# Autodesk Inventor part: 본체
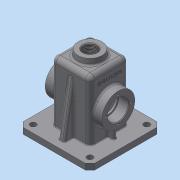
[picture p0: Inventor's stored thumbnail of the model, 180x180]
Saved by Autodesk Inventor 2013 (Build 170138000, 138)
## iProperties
Created: 2018-10
Part Number: 본체
Material: 일반
Document SubType Name: Modeling
Designer: Administrator
Density: 1 g/cm^3
Mass: 294.038 g
Surface Area: 900.166 cm^2
Volume: 294.038 cm^3
Author: Administrator
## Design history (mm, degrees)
sketch "스케치1"
  geometry: L1 (-32.5, -32.5)-(32.5, -32.5); L2 (32.5, -32.5)-(32.5, 32.5); L3 (32.5, 32.5)-(-32.5, 32.5); L4 (-32.5, 32.5)-(-32.5, -32.5); L5 (-32.5, -32.5)-(32.5, 32.5); L6 (32.5, -32.5)-(-32.5, 32.5); 1 further point
  constraints: 12 end point, 2 midpoint, 2 parallel, 1 horizontal, 1 perpendicular
  dimensions: "d0" = 65 distance of L3.end L2.end; "d1" = 65 distance of L2.end L1.end
extrude "돌출1" new body sketch "스케치1" stored distance "d2" = 110; taper "d3" = 0 deg
feature "쉘1" dims "d4" = 5
sketch "스케치2"
  geometry: L1 (-32.5, -32.5)-(32.5, -32.5) reference; L2 (32.5, -32.5)-(32.5, 32.5) reference; L3 (32.5, 32.5)-(-32.5, 32.5) reference; L4 (-32.5, 32.5)-(-32.5, -32.5) reference; L5 (-60, -60)-(60, -60); L6 (60, -60)-(60, 60); L7 (60, 60)-(-60, 60); L8 (-60, 60)-(-60, -60); L9 (-60, -60)-(60, 60); L10 (60, -60)-(-60, 60); 1 further point
  constraints: 12 end point, 2 midpoint, 2 parallel, 1 horizontal, 1 perpendicular
  dimensions: "d5" = 120 distance of L7.end L6.end; "d6" = 120 distance of L6.end L5.end
extrude "돌출2" join sketch "스케치2" distance "d7" = 10; taper "d8" = 0 deg
node "작업 평면1"
sketch "스케치3"
  geometry: C1 r 20 at (0, 0); 1 further point
  constraints: 1 centre point, 1 coincident
  dimensions: "d10" = 40 diameter of C1
extrude "돌출3" join sketch "스케치3" stored distance "d11" = 10; taper "d12" = 7 deg
fillet "모깎기1" dims "d13" = 8
node "작업 평면2"
sketch "스케치5"
  geometry: C1 r 27.5 at (47, 24.5); 1 further point
  constraints: 1 centre point, 1 coincident
  dimensions: "d15" = 55 diameter of C1
extrude "돌출4" join sketch "스케치5" stored distance "d16" = 10; taper "d17" = 0 deg
sketch "스케치6"
  geometry: C1 r 27.5 at (0, 0) reference
hole "구멍1" sketch "스케치6" at (0, 0) diameter "d18" = 30; stored, may be unused: countersink angle "d22" = 90 deg, drill point angle "d24" = 0 deg; dims "d19" = 6, "d20" = 35, "d21" = 17, "d23" = 8
sketch "스케치7"
  geometry: L1 (0, 0)-(-21, 0); C1 r 27.5 at (0, 0) reference; 1 further point
  constraints: 2 end point, 1 coincident, 1 horizontal
  dimensions: "d25" = 21 distance of L1.start L1.end
hole "구멍2" sketch "스케치7" at (-21, 0) diameter "d26" = 3.459; stored, may be unused: countersink angle "d30" = 90 deg, drill point angle "d32" = 118 deg; dims "d27" = 8, "d28" = 35, "d29" = 17, "d31" = 10
fillet "모깎기2" dims "d36" = 3
fillet "모깎기3" dims "d37" = 3
sketch "스케치8"
  geometry: C1 r 20 at (0, 0) reference
hole "구멍3" sketch "스케치8" at (0, 0) diameter "d38" = 22.835; stored, may be unused: countersink angle "d42" = 90 deg, drill point angle "d44" = 118 deg; dims "d39" = 8, "d40" = 35, "d41" = 17, "d43" = 10
sketch "스케치9"
  geometry: L1 (42.358, -13)-(48, -45); L2 (60, -45)-(-60, -45) reference; L3 (60, -55)-(60, -45) reference; 1 further point
  constraints: 2 end point, 1 point on line
  dimensions: "d46" = 10 deg angle of L1 L3; "d47" = 12 distance from line of L1.end L3
feature "리브1" sketch "스케치9" dims "d48" = 1, "d49" = 10, "d50" = 0, "d51" = 0, "d52" = 1, "d53" = 1
sketch "스케치10"
  geometry: L1 (42.5, -31)-(42.5, -45); L2 (27.5, 50)-(27.5, -55) reference; L3 (30.5, -15)-(30.5, -17.5) reference; L4 (30.5, -17.5)-(47.5, -17.5) reference; L5 (47.5, -17.5)-(47.5, -19.271) reference; L6 (47.5, -19.271)-(37.5, -19.271) reference; L7 (37.5, -19.271)-(36.461, -21) reference; L8 (36.461, -21)-(37.5, -22.73) reference; L9 (37.5, -22.73)-(47.5, -22.73) reference; L10 (47.5, -22.73)-(47.5, -27.5) reference; L11 (47.5, -27.5)-(35.5, -27.5) reference; L12 (32.5, -30.5)-(32.5, -45) reference; L13 (32.5, -45)-(60, -45) reference; L14 (60, -45)-(60, -55) reference; L15 (60, -55)-(27.5, -55) reference; L16 (27.5, -55)-(27.5, -15) reference; L17 (27.5, -15)-(30.5, -15) reference; L18 (36.461, 21)-(37.5, 19.271) reference; L19 (37.5, 19.271)-(47.5, 19.271) reference; L20 (47.5, 19.271)-(47.5, 17.5) reference; L21 (47.5, 17.5)-(30.5, 17.5) reference; L22 (30.5, 17.5)-(30.5, 15) reference; L23 (30.5, 15)-(27.5, 15) reference; L24 (27.5, 15)-(27.5, 50) reference; L25 (27.5, 50)-(11.418, 50) reference; L26 (11.418, 50)-(11.418, 65) reference; L27 (11.418, 65)-(20, 65) reference; L28 (20, 65)-(21.228, 55) reference; L29 (21.228, 55)-(24.5, 55) reference; L30 (32.5, 47)-(32.5, 30.5) reference; L31 (35.5, 27.5)-(47.5, 27.5) reference; L32 (47.5, 27.5)-(47.5, 22.73) reference; L33 (47.5, 22.73)-(37.5, 22.73) reference; L34 (37.5, 22.73)-(36.461, 21) reference; L35 (-30.5, -17.5)-(-30.5, -15) reference; L36 (-30.5, -15)-(-27.5, -15) reference; L37 (-27.5, -15)-(-27.5, -55) reference; L38 (-27.5, -55)-(-60, -55) reference; L39 (-60, -55)-(-60, -45) reference; L40 (-60, -45)-(-32.5, -45) reference; L41 (-32.5, -45)-(-32.5, -30.5) reference; L42 (-35.5, -27.5)-(-47.5, -27.5) reference; L43 (-47.5, -27.5)-(-47.5, -22.73) reference; L44 (-47.5, -22.73)-(-37.5, -22.73) reference; L45 (-37.5, -22.73)-(-36.461, -21) reference; L46 (-36.461, -21)-(-37.5, -19.271) reference; L47 (-37.5, -19.271)-(-47.5, -19.271) reference; L48 (-47.5, -19.271)-(-47.5, -17.5) reference; L49 (-47.5, -17.5)-(-30.5, -17.5) reference; L50 (-30.5, 15)-(-30.5, 17.5) reference; L51 (-30.5, 17.5)-(-47.5, 17.5) reference; L52 (-47.5, 17.5)-(-47.5, 19.271) reference; L53 (-47.5, 19.271)-(-37.5, 19.271) reference; L54 (-37.5, 19.271)-(-36.461, 21) reference; L55 (-36.461, 21)-(-37.5, 22.73) reference; L56 (-37.5, 22.73)-(-47.5, 22.73) reference; L57 (-47.5, 22.73)-(-47.5, 27.5) reference; L58 (-47.5, 27.5)-(-35.5, 27.5) reference; L59 (-32.5, 30.5)-(-32.5, 47) reference; L60 (-24.5, 55)-(-21.228, 55) reference; L61 (-21.228, 55)-(-20, 65) reference; L62 (-20, 65)-(-11.418, 65) reference; L63 (-11.418, 65)-(-11.418, 50) reference; L64 (-11.418, 50)-(-27.5, 50) reference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; A1 r 3 centre (35.5, -30.5) between (35.5, -27.5) and (32.5, -30.5) reference; A2 r 8 centre (24.5, 47) between (32.5, 47) and (24.5, 55) reference; A3 r 3 centre (35.5, 30.5) between (32.5, 30.5) and (35.5, 27.5) reference; A4 r 3 centre (-35.5, -30.5) between (-32.5, -30.5) and (-35.5, -27.5) reference; A5 r 3 centre (-35.5, 30.5) between (-35.5, 27.5) and (-32.5, 30.5) reference; A6 r 8 centre (-24.5, 47) between (-24.5, 55) and (-32.5, 47) reference; 1 further point
  constraints: 2 end point, 1 point on line, 1 vertical
  dimensions: "d54" = 15 distance between parallel lines of L1 L2
feature "리브2" sketch "스케치10" dims "d55" = 1, "d56" = 6, "d57" = 0, "d58" = 0, "d59" = 1, "d60" = 1
chamfer "모따기1" distance "d61" = 8; stored, may be unused: second distance "d62" = 2, angle "d63" = 45 deg
sketch "스케치11"
  geometry: C1 r 5 at (-47.5, 47.5); 1 further point
  constraints: 1 centre point
  dimensions: "d64" = 10 diameter of C1; "d65" = 47.5 horizontal distance of C1.centre point (0, 0); "d66" = 47.5 horizontal distance of C1.centre point (0, 0)
extrude "돌출5" cut sketch "스케치11" stored distance "d67" = 10; taper "d68" = 0 deg
fillet "모깎기4" dims "d72" = 3
fillet "모깎기5" dims "d73" = 0.3
fillet "모깎기6" dims "d74" = 3
chamfer "모따기2" distance "d75" = 1; stored, may be unused: second distance "d76" = 2, angle "d77" = 45 deg
sketch "스케치12"
  geometry: L1 (0, -8)-(92, -8) reference; L2 (-18, 4.5)-(-18, 44.5) reference; 1 further point
  constraints: 1 other
  dimensions: "d78" = 32.5 distance from line of L1 point (8, 24.5); "d79" = 26 distance from line of point (8, 24.5) L2
feature "엠보싱1" sketch "스케치12" dims "d5" = 120, "d6" = 120, "d80" = 0.5, "d81" = 0
fillet "모깎기11" dims "d86" = 3
fillet "모깎기12" dims "d87" = 3
fillet "모깎기13" dims "d88" = 1
node "솔리드1"
pattern_circular "원형 패턴1" dims angle "d34" = 360 deg
mirror "대칭1"
mirror "대칭2"
mirror "대칭3"
pattern_linear "직사각형 패턴1" dims "d71" = 95
mirror "대칭4"
node "절단 모서리 투영1"
other parameters: "d14" = 15
